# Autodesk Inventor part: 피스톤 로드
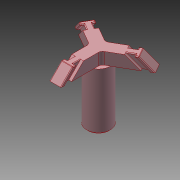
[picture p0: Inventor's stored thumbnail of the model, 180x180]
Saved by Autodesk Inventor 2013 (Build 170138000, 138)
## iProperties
Created: 2023-03
Part Number: 피스톤 로드
Material: 강철, 연강
Document SubType Name: Modeling
Designer: mdu-01
Density: 1 g/cm^3
Author: mdu-01
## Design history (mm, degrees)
sketch "스케치1"
  geometry: L1 (0, 0)-(0, 29); L2 (0, 29)-(8, 21); L3 (8, 21)-(8, 0); L4 (8, 0)-(0, 0); L5 (0, 26.172)-(8, 18.172); L6 (0, 21.929)-(8, 13.929)
  constraints: 12 end point, 4 point on line, 3 parallel, 1 perpendicular, 1 vertical
  dimensions: "d0" = 45 deg angle of L1 L2; "d1" = 29 distance of L1.start L1.end; "d2" = 8 distance between parallel lines of L3 L1; "d3" = 2 distance between parallel lines of L5 L2; "d4" = 3 distance between parallel lines of L6 L5
extrude "돌출1" new body sketch "스케치1" stored distance "d5" = 7.8; taper "d6" = 0 deg
extrude "돌출2" join sketch "스케치1" stored distance "d7" = 4; taper "d8" = 0 deg
fillet "모깎기5" dims "d31" = 0.5
fillet "모깎기3" dims "d14" = 3
sketch "스케치3"
  geometry: C1 r 8 at (-2, -21.929); 1 further point
  constraints: 1 centre point, 1 coincident
  dimensions: "d32" = 16 diameter of C1
extrude "돌출4" join sketch "스케치3" distance "d33" = 38; taper "d34" = 0 deg
chamfer "모따기2" distance "d35" = 1; stored, may be unused: second distance "d36" = 2, angle "d37" = 45 deg
hole "구멍2" diameter "d40" = 6.647; stored, may be unused: countersink angle "d44" = 90 deg, drill point angle "d46" = 118 deg; dims "d38" = 10, "d39" = 10, "d41" = 16, "d42" = 4, "d43" = 2, "d45" = 18
node "솔리드1"
pattern_circular "원형 패턴1" dims "d12" = 360 deg
